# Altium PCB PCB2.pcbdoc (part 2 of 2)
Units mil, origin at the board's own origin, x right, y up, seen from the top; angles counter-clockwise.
Board outline 4645 x 3125 mil, 2 copper layers (Top Layer, Bottom Layer); 221 components, 102 nets, 399 pads, 608 vias.
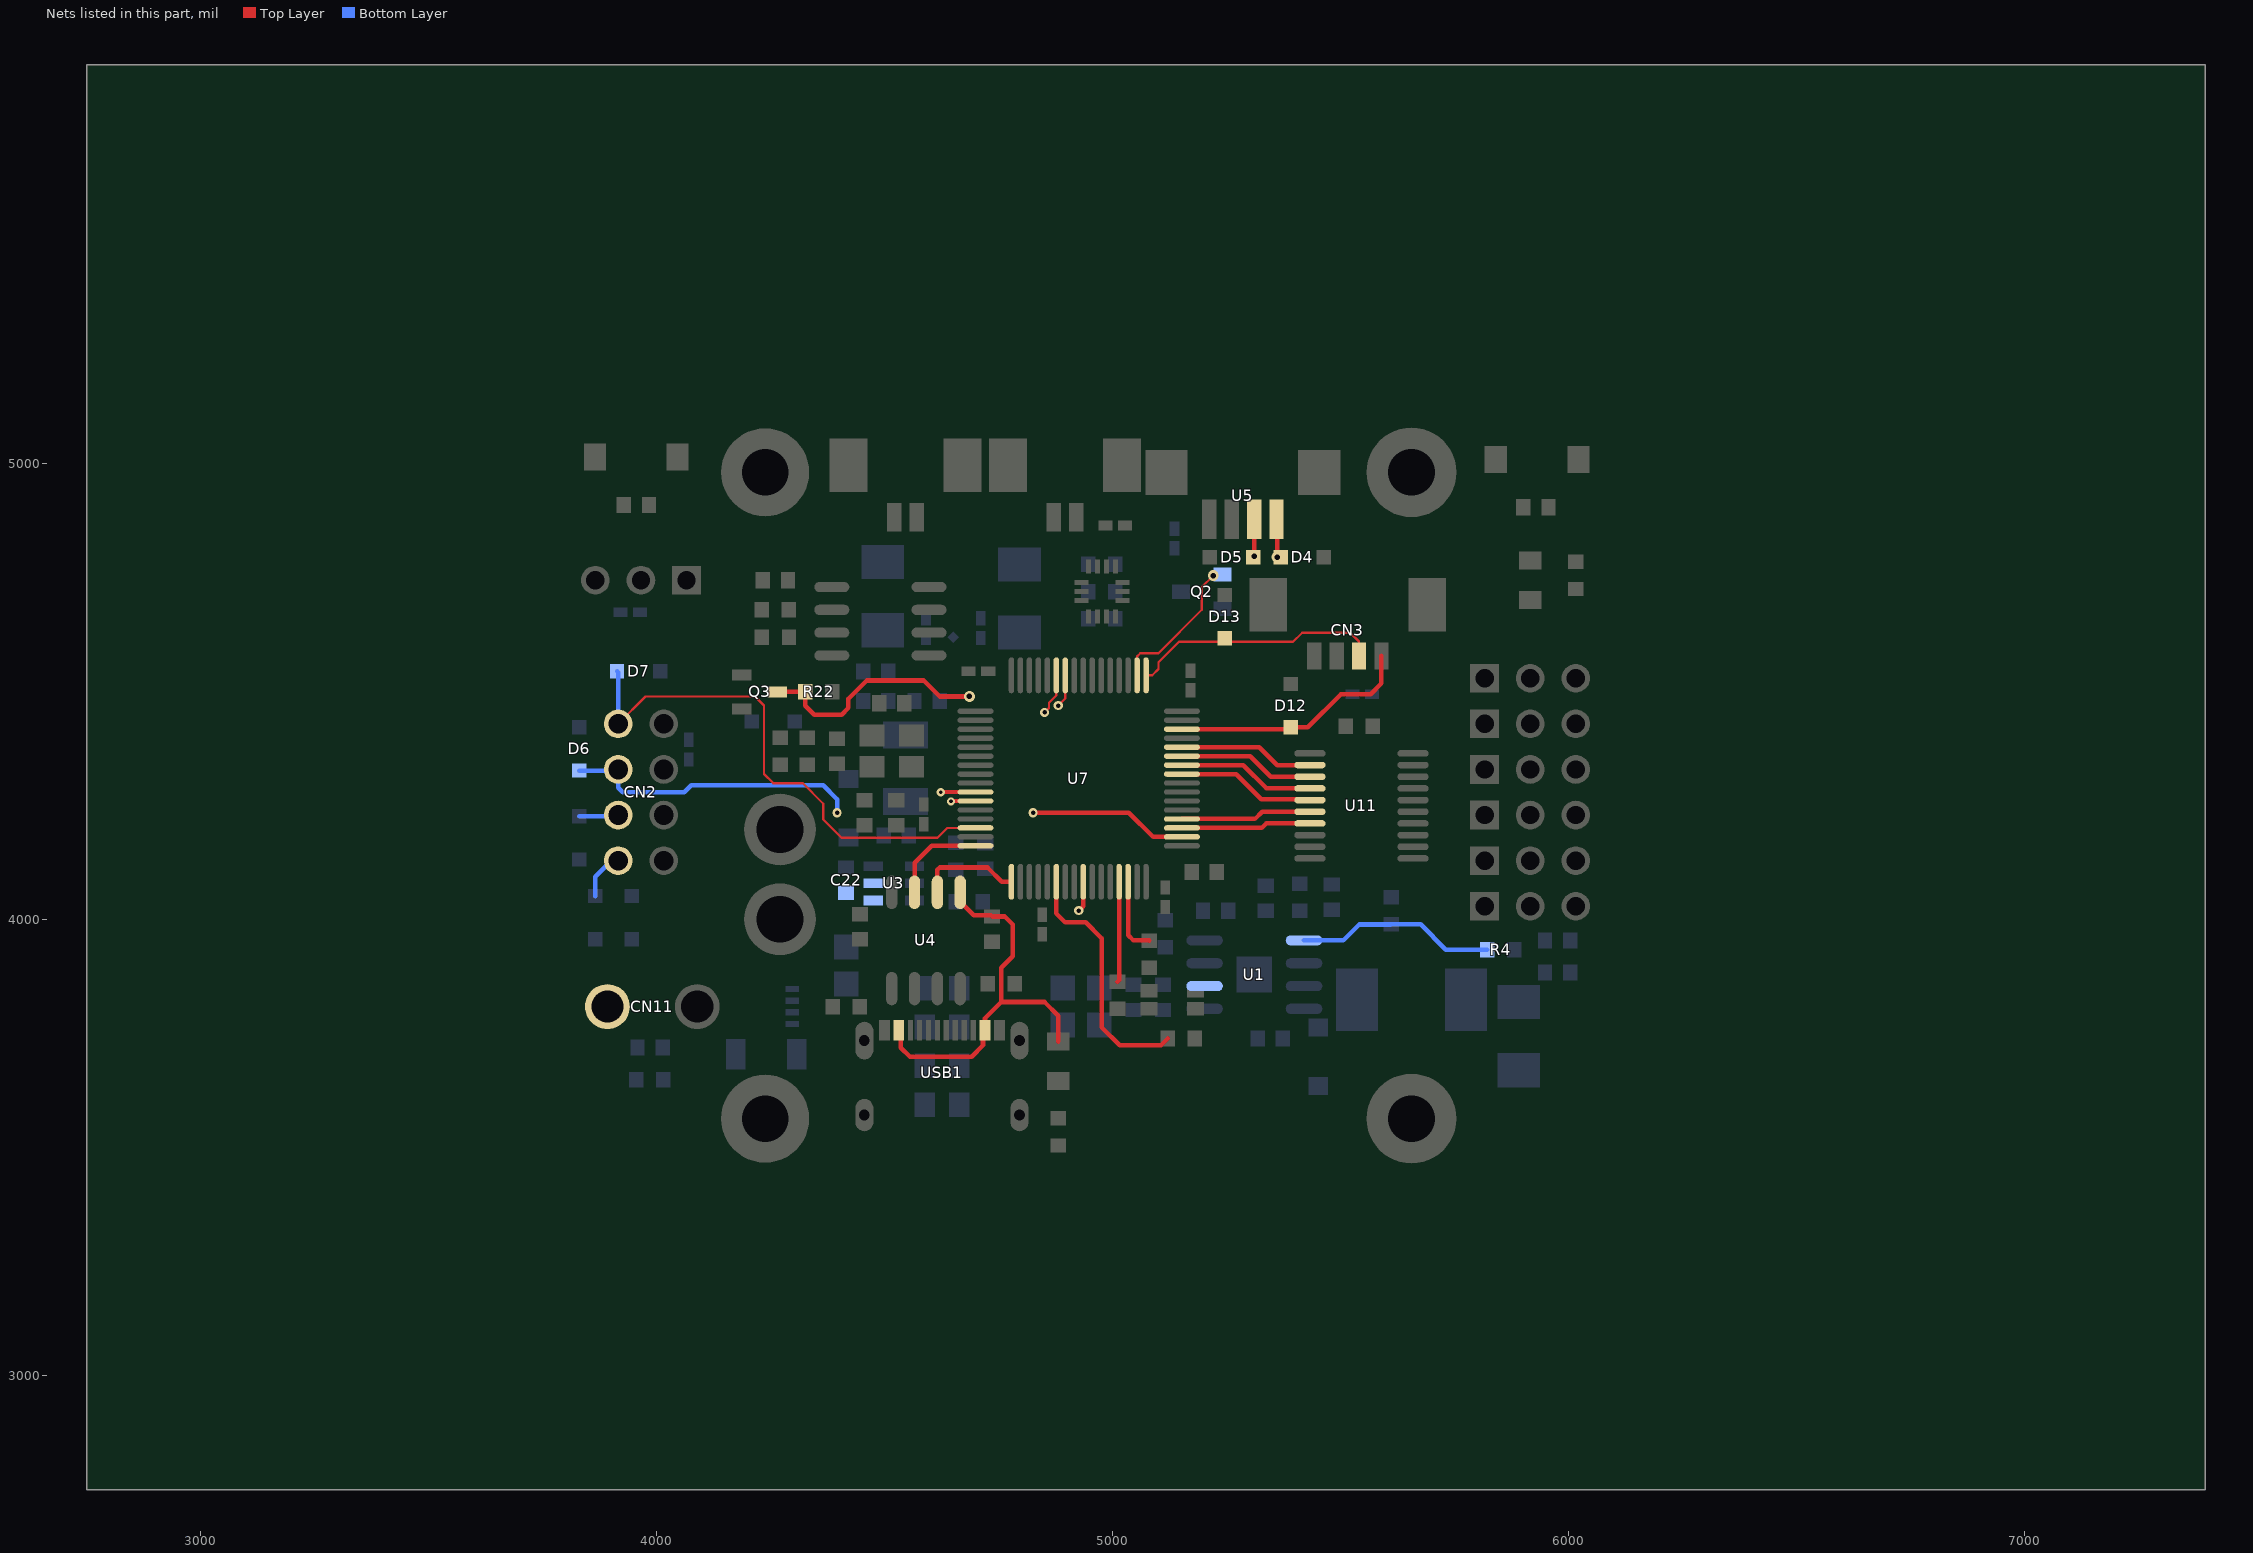
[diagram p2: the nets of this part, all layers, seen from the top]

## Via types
v1: diameter 17.76, hole 9.65, Top Layer to Bottom Layer, 499 vias
v2: diameter 24.02, hole 12.01, Top Layer to Bottom Layer, 75 vias
v3: diameter 17.76, hole 8, Top Layer to Bottom Layer, 19 vias
v4: diameter 20, hole 10, Top Layer to Bottom Layer, 11 vias
v5: diameter 24, hole 12, Top Layer to Bottom Layer, 4 vias

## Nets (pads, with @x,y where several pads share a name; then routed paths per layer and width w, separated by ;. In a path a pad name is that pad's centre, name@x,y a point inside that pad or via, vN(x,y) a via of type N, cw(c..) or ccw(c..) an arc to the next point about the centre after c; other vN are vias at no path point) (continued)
SPI2_CS: CN2.1 D7.1 U7.14 | length 1170.3
  Top Layer w5: CN2.1@3915,4430 3975,4490 4215,4490 4235,4470 4235,4320 4255,4300 4320,4300 4365,4255 4365,4220 4405,4180 4615,4180 4636.73,4201.73 U7.14@4698.63,4201.73
  Bottom Layer w10: D7.1@3912.6,4545 3915,4542.6 CN2.1@3915,4430
SPI2_MISO: CN2.7 U7.10 | length 1164.3
  Top Layer w8: v3(4622.37,4280) 4622.84,4280.47 U7.10@4698.63,4280.47
  Mid-Layer 2 w10: CN2.7@3915,4130 3895,4130 3855,4170 3855,4255 3880,4280 4115,4280 4165,4330 4345,4330 4395,4280 v3(4622.37,4280)
  Bottom Layer w10: 3865,4052.4 3865,4095 3900,4130 CN2.7@3915,4130
SPI2_MOSI: CN2.5 U7.11 | length 964.6
  Top Layer w8: v3(4645,4260) 4645.79,4260.79 U7.11@4698.63,4260.79
  Mid-Layer 2 w10: CN2.5@3915,4230 3915,4210 3945,4180 4100,4180 4215,4295 4355,4295 4390,4260 v3(4645,4260)
  Bottom Layer w10: 3830,4227.4 3912.4,4227.4 CN2.5@3915,4230
SPI2_SCL: CN2.3 D6.1 U7.34 | length 1437.1
  Top Layer w10: v4(4825,4235) 5035,4235 5087.95,4182.05 U7.34@5151.37,4182.05
  Mid-Layer 2 w10: v4(4395,4235) v4(4825,4235)
  Bottom Layer w10: D6.1@3830,4327.6 3912.6,4327.6 CN2.3@3915,4330 3915,4290 3925,4280 4060,4280 4075,4295 4365,4295 4395,4265 v4(4395,4235)
SWD_CLK: CN3.2 D13.1 U7.49 | length 554.1
  Top Layer w5: U7.49@5072.64,4536.37 5086.37,4536.37 5100,4550 5100,4565 5145,4610 5395,4610 5415,4630 5520,4630 5539.6,4610.4 CN3.2@5539.6,4578.9
SWD_IO: D12.1 U7.46 | length 539.2
  Top Layer w10: U7.46@5151.37,4418.27 5385.67,4418.27 D12.1@5390,4422.6 5427.6,4422.6 5500,4495 5565,4495 5588.8,4518.8 5588.8,4578.9
TIM1_CH1: U7.41 U11.5 | length 304.2
  Top Layer w10: U7.41@5151.37,4319.84 5270.16,4319.84 5325,4265 5429.76,4265 U11.5@5431.97,4262.79
TIM1_CH2: U7.42 U11.4 | length 301.8
  Top Layer w10: U7.42@5151.37,4339.53 5285.47,4339.53 5336.61,4288.39 U11.4@5431.97,4288.39
TIM1_CH3: U7.43 U11.3 | length 299.3
  Top Layer w10: U7.43@5151.37,4359.21 5300.79,4359.21 5346.02,4313.98 U11.3@5431.97,4313.98
TIM1_CH4: U7.44 U11.2 | length 296.9
  Top Layer w10: U7.44@5151.37,4378.9 5321.1,4378.9 5360.43,4339.57 U11.2@5431.97,4339.57
TIM2_CH1: Q2.1 U7.50 | length 311.3
  Top Layer w5: U7.50@5052.95,4536.37 5052.95,4577.95 5060,4585 5100,4585 5195,4680 5195,4730 v2(5220,4755)
TIM2_CH2: 
TIM2_CH3: U7.29 | length 220.5
  Top Layer w10: 5010,3864.66 5013.58,3868.24 U7.29@5013.58,4083.63
TIM2_CH4: U7.30 | length 168.6
  Top Layer w10: U7.30@5033.27,4083.63 5033.27,3966.73 5045,3955 5079.66,3955 5080,3954.66
TIM15_CH1: U7.35 U11.7 | length 284.7
  Top Layer w10: U7.35@5151.37,4201.73 5326.73,4201.73 5336.61,4211.61 U11.7@5431.97,4211.61
TIM15_CH2: U7.36 U11.6 | length 287.1
  Top Layer w10: U7.36@5151.37,4221.42 5311.42,4221.42 5327.2,4237.2 U11.6@5431.97,4237.2
TIM16_CH1: U7.22 | length 554.2
  Top Layer w10: U7.22@4875.79,4083.63 4875.79,4014.21 4895,3995 4940,3995 4975,3960 4975,3765 5015,3725 5105.34,3725 5120.34,3740
UART1_RX: D4.1 U5.1 U7.59 | length 915.6
  Top Layer w5: v4(4850,4455) 4860,4465 4860,4476.16 4875.79,4491.95 U7.59@4875.79,4536.37
  Top Layer w10: U5.1@5358.82,4878.97 5360,4877.79 v2(5360,4795.57)
  Mid-Layer 2 w10: v4(4850,4455) 4900,4405 5050,4405 5360,4715 v2(5360,4795.57)
UART1_TX: D5.1 U5.2 U7.58 | length 811.5
  Top Layer w5: v4(4880,4470) 4895.47,4485.47 U7.58@4895.47,4536.37
  Top Layer w10: U5.2@5309.6,4878.97 5310,4878.57 v2(5310,4797.05)
  Mid-Layer 2 w10: v4(4880,4470) 4925,4425 5030,4425 5310,4705 v2(5310,4797.05)
UART2_RX: U4.6 U7.17 | length 226.8
  Top Layer w10: U4.6@4615,4060.61 4615,4110 4620,4115 4725,4115 4756.37,4083.63 U7.17@4777.36,4083.63
UART2_TX: U4.7 U7.16 | length 213.5
  Top Layer w10: U4.7@4565,4060.61 4565,4125 4602.36,4162.36 U7.16@4698.63,4162.36
UART3_RX: Q3.3 R22.1 U7.25 | length 1185.4
  Top Layer w10: Q3.3@4263.98,4500 R22.1@4325.68,4500 4325.68,4469.32 4345,4450 4405,4450 4420,4465 4420,4485 4460,4525 4585,4525 4620,4490 v2(4685,4490) ; v4(4925,4020.46) 4934.84,4030.3 U7.25@4934.84,4083.63
  Mid-Layer 2 w10: v2(4685,4490) 4740,4490 4925,4305 v4(4925,4020.46)
UART3_TX: 
USB_5V: U4.5 USB1.A4B9 USB1.B4A9 | length 880.9
  Top Layer w10: USB1.A4B9@4530.5,3758 4535,3753.5 4535,3720 4555,3700 4690,3700 4715,3725 4715,3753.5 USB1.B4A9@4719.5,3758 4719.5,3784.5 4755,3820 ; U4.5@4665,4060.61 4665,4040 4695,4010 4732.56,4010 4735,4007.56 4762.44,4007.56 4780,3990 4780,3920 4755,3895 4755,3820 ; 4880,3733.31 4880,3790 4850,3820 4755,3820
VCC: C22.1 CN11.2 U1.2 U3.4 U3.5
VREF1: R4.1 U1.5 | length 438.9
  Bottom Layer w10: U1.5@5419,3955 5505,3955 5540,3990 5609.66,3990 5610,3990.34 5674.66,3990.34 5730,3935 R4.1@5820.34,3935
"": 
pads on no net: C1.2 C2.2 C3.2 C4.2 C5.2 C6.2 C7.2 C8.2 C9.2 C10.2 C11.2 C12.1 C13.2 C14.2 C15.2 C16.2 C17.2 C18.1 C19.1 C20.2 C21.2 C22.2 C23.2 C24.2 C25.2 C26.2 C27.2 C28.2 C29.2 C30.2 C31.2 C32.2 C33.2 C34.2 C35.2 C36.2 C37.2 C38.2 C39.2 C40.2 C41.2 C42.2 C43.2 CN2.8 CN3.1 CN11.1 CN12.1 D1.1 D2.2 D3.1 D4.2 D5.2 D6.2 D7.2 D8.2 D9.2 D10.2 D11.2 D12.2 D13.2 H1.1 H4.1 L1.1 L2.2 LED1.2 LED2.2 LED3.1 Q1.4 Q2.2 Q3.1 R1.2 R2.2 R3.2 R4.2 R5.2 R6.2 R7.2 R8.2 R9.2 R10.2 R11.2 R12.2 R13.2 R14.2 R15.2 R16.2 R17.2 R18.2 R19.2 R20.2 R21.2 R22.2 R23.2 R24.2 R25.2 R26.2 R27.2 SW1.2 SW2.2 U1.1 U2.5 U3.6 U4.1 U4.4 U5.6 U6.1 U7.2 U7.3 U7.4 U7.15 U7.20 U7.21 U7.23 U7.24 U7.27 U7.28 U7.37 U7.38 U7.39 U7.40 U7.51 U7.64 U8.1 U8.2 U8.3 U8.10 U8.11 U9.1 U10.1 U11.1 U11.8 U11.9 U11.11 U11.12 U23.3 U24.3 U25.3 U26.3 U27.3 U28.3 U29.3 USB1.A1B12 USB1.A8 USB1.B8 X1.1
copper on no net:
  other v5: 5290.3,3860.3 5329.7,3860.3 5290.3,3899.7 5329.7,3899.7

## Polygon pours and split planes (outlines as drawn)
GND on Mid-Layer 1 (solid, remove dead copper, pour order 2): 3460,3165 6640,3165 6640,5340 3460,5340
GND on Top Layer (solid, remove dead copper, pour order 4): 3115,3000 6910,3000 6910,5540 3115,5540
GND on Mid-Layer 2 (solid, remove dead copper, pour order 5): 3000,3030 7145,3030 7145,5625 3000,5625
GND on Bottom Layer (solid, remove dead copper, pour order 6): 3415,3210 6460,3210 6460,5410 3415,5410
PGND on Mid-Layer 1 (solid, remove dead copper): 4625,3391.93 4625,3905 5050.31,3905 5055.9,3899.41 5055.9,4026.87 5054.24,4028.54 5154.59,4028.54 5155,4028.13 5155,4059.78 5279.78,4059.78 5280,4060 5280,4105 5701.03,4105 5701.3,4104.73 5759.73,4104.73 5760,4105 5760,4600 6180,4600 6180,3395 6185,3390 4626.93,3390
PGND on Bottom Layer (solid, remove dead copper, pour order 1): 5279.78,4059.78 5280,4060 5280,4105 5701.03,4105 5701.3,4104.73 5759.73,4104.73 5760,4105 5760,4600 6180,4600 6180,3395 6185,3390 4626.93,3390 4625,3391.93 4625,3905 4955,3905 4955,4060
PGND on Top Layer (solid, remove dead copper, pour order 3): 5279.78,4059.78 5280,4060 5280,4105 5701.03,4105 5701.3,4104.73 5759.73,4104.73 5760,4105 5760,4600 6180,4600 6180,3395 6185,3390 4626.93,3390 4625,3391.93 4625,3905 4955,3905 4955,4060

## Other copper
Top Layer:
  region net VCC: 3780,3755 3980,3755 4005,3780 4005,3860 4044.2,3899.2 4348.7,3899.2 4348.7,4083.7 4350,4085 4156.6,4085 4111.6,4040 3785,4040 3780,4035
  pour cut-out net $1N6780: 5982.99,4793.31 5982.99,4783.31 5997.99,4770.81 5997.99,4800.88
  pour cut-out net PGND: 6020,4694.8 6032.01,4709.8 5997.99,4709.8 6010,4694.8
  pour cut-out net SER.5V: 5920,4667.01 5932.5,4682.01 5897.5,4682.01 5910,4667.01
  pour cut-out net $1N6780: 5954.61,4793.31 5939.61,4805.81 5939.61,4770.81 5954.61,4783.31
  pour cut-out net USB_5V: 4710,3725 4720,3725 4731.3,3735.35 4707.7,3735.35
  pour cut-out net USB_5V: 4714.5,3784.5 4707.7,3780.65 4731.3,3780.65 4724.5,3784.5
  pour cut-out net $2N2059: 4689.9,3792.65 4688,3780.65 4699.8,3780.65 4697.9,3792.65
  pour cut-out net DP: 4650.5,3790.5 4648.6,3780.65 4660.4,3780.65 4658.5,3790.5
  pour cut-out net DN: 4631,3725 4639,3725 4640.7,3735.35 4628.9,3735.35
  pour cut-out net DP: 4611.2,3784.8 4609.3,3780.65 4621.1,3780.65 4619.2,3784.8
  pour cut-out net DN: 4591.5,3784.5 4589.6,3780.65 4601.4,3780.65 4599.5,3784.5
  pour cut-out net DN: 4599.5,3724.5 4601.4,3735.35 4589.6,3735.35 4591.5,3724.5
  pour cut-out net $2N2060: 4571.8,3784.2 4569.9,3780.65 4581.7,3780.65 4579.8,3784.2
  pour cut-out net $2N2059: 4721.34,3840 4729.34,3840 4739.34,3842.99 4711.34,3842.99
  pour cut-out net DP: 4534.16,3888.5 4528.06,3893.71 4502.6,3873.7 4527.4,3867.6
  pour cut-out net $2N2114: 4487.6,4055.61 4502.6,4043.11 4502.6,4078.11 4487.6,4065.61
  pour cut-out net UART2_TX: 4570,4111.27 4560,4111.27 4552.6,4084.92 4577.4,4084.92
  pour cut-out net UART2_RX: 4610,4110 4602.6,4084.92 4627.4,4084.92 4620,4110
  pour cut-out net USB_5V: 4682.53,4015.4 4687.91,4024.16 4677.4,4052.35 4652.6,4036.3
  pour cut-out net USB_5V: 4762.44,4002.56 4762.44,4012.56 4752.72,4023.31 4752.72,3991.81
  pour cut-out net USB_5V: 4702.28,4005 4717.28,3992.5 4717.28,4023.31 4702.28,4015
  pour cut-out net $2N2114: 4450,4035 4440,4035 4427.5,4028.31 4462.5,4028.31
  pour cut-out net USB_5V: 4885,3767.99 4875,3767.99 4862.5,3752.99 4897.5,3752.99
  pour cut-out net $2N2074: 4875,3612 4885,3612 4897.5,3627 4862.5,3627
  pour cut-out net $2N2074: 4875,3595.54 4862.99,3580.54 4897.01,3580.54 4885,3595.54
  pour cut-out net 3V3: 4756.45,4531.37 4771.45,4518.87 4771.45,4553.87 4756.45,4541.37
  pour cut-out net CAN_TX: 4811.73,4587.98 4810.82,4569.83 4822.64,4569.83 4821.73,4587.98
  pour cut-out net CAN_RX: 4831.42,4587.98 4830.51,4569.83 4842.33,4569.83 4841.42,4587.98
  pour cut-out net UART1_RX: 4878.29,4491.95 4881.7,4502.91 4869.88,4502.91 4873.29,4491.95
  pour cut-out net UART1_TX: 4892.97,4490.06 4897.97,4490.06 4901.38,4502.91 4889.56,4502.91
  pour cut-out net SPI1_MOSI: 4910.16,4484.76 4920.16,4484.76 4921.07,4502.91 4909.25,4502.91
  pour cut-out net SPI1_MISO: 4937.34,4582.68 4932.34,4582.68 4928.93,4569.83 4940.75,4569.83
  pour cut-out net SPI1_CS: 4969.21,4490.79 4979.21,4490.79 4980.12,4502.91 4968.3,4502.91
  pour cut-out net BMI160_INT1: 4996.4,4582.68 4991.4,4582.68 4987.99,4569.83 4999.81,4569.83
  pour cut-out net TIM2_CH1: 5050.45,4577.95 5047.04,4569.83 5058.86,4569.83 5055.45,4577.95
  pour cut-out net SWD_CLK: 5086.05,4538.87 5078.55,4545.12 5078.55,4527.62 5086.05,4533.87
  pour cut-out net 3V3: 5160.81,4474.15 5117.91,4463.55 5170.21,4451.73 5173.54,4472.73
  pour cut-out net SWD_IO: 5202.98,4423.27 5184.83,4424.18 5184.83,4412.36 5202.98,4413.27
  pour cut-out net DIR: 5202.98,4403.58 5184.83,4404.49 5184.83,4392.67 5202.98,4393.58
  pour cut-out net TIM1_CH4: 5202.98,4383.9 5184.83,4384.81 5184.83,4372.99 5202.98,4373.9
  pour cut-out net TIM1_CH3: 5202.98,4364.21 5184.83,4365.12 5184.83,4353.3 5202.98,4354.21
  pour cut-out net TIM1_CH2: 5202.98,4334.53 5202.98,4344.53 5184.83,4345.44 5184.83,4333.62
  pour cut-out net TIM1_CH1: 5202.98,4324.84 5184.83,4325.75 5184.83,4313.93 5202.98,4314.84
  pour cut-out net TIM15_CH2: 5202.98,4226.42 5184.83,4227.33 5184.83,4215.51 5202.98,4216.42
  pour cut-out net TIM15_CH1: 5202.98,4206.73 5184.83,4207.64 5184.83,4195.82 5202.98,4196.73
  pour cut-out net SPI2_SCL: 5099.76,4177.05 5117.91,4176.14 5117.91,4187.96 5099.76,4187.05
  pour cut-out net SERVO_EN: 5192.64,4167.36 5184.83,4168.27 5184.83,4156.45 5192.64,4157.36
  pour cut-out net 3V3: 5088.35,4075 5078.55,4117.09 5066.73,4064.79 5081.27,4067.92
  pour cut-out net TIM2_CH4: 5038.27,4032.02 5039.18,4050.17 5027.36,4050.17 5028.27,4032.02
  pour cut-out net TIM2_CH3: 5018.58,4032.02 5019.49,4050.17 5007.67,4050.17 5008.58,4032.02
  pour cut-out net KEY: 4959.53,4032.02 4960.44,4050.17 4948.62,4050.17 4949.53,4032.02
  pour cut-out net UART3_RX: 4939.84,4032.02 4940.75,4050.17 4928.93,4050.17 4929.84,4032.02
  pour cut-out net TIM16_CH1: 4870.79,4032.02 4880.79,4032.02 4881.7,4050.17 4869.88,4050.17
  pour cut-out net 3V3: 4821.73,4039.73 4822.64,4050.17 4810.82,4050.17 4811.73,4039.73
  pour cut-out net 3V3: 4811.73,4135.24 4810.82,4117.09 4822.64,4117.09 4821.73,4135.24
  pour cut-out net UART2_RX: 4756.45,4088.63 4756.45,4078.63 4771.45,4066.13 4771.45,4101.13
  pour cut-out net UART2_TX: 4647.02,4157.36 4665.17,4156.45 4665.17,4168.27 4647.02,4167.36
  pour cut-out net SPI2_CS: 4652.32,4199.23 4665.17,4195.82 4665.17,4207.64 4652.32,4204.23
  pour cut-out net 3V3: 4647.02,4226.42 4647.02,4216.42 4665.17,4215.51 4665.17,4227.33
  pour cut-out net 3V3: 4750.24,4226.42 4732.09,4227.33 4732.09,4215.51 4750.24,4216.42
  pour cut-out net SPI2_MOSI: 4648.82,4256.79 4665.17,4254.88 4665.17,4266.7 4648.82,4264.79
  pour cut-out net SPI2_MISO: 4648.82,4276.47 4665.17,4274.56 4665.17,4286.38 4648.82,4284.47
  pour cut-out net I2C3_SDA: 4648.82,4296.16 4665.17,4294.25 4665.17,4306.07 4648.82,4304.16
  pour cut-out net I2C3_SCL: 4648.82,4315.84 4665.17,4313.93 4665.17,4325.75 4648.82,4323.84
  pour cut-out net RST: 4646.38,4335 4665.17,4333.62 4665.17,4345.44 4647.94,4345
  pour cut-out net OSC_OUT: 4652.32,4356.71 4665.17,4353.3 4665.17,4365.12 4652.32,4361.71
  pour cut-out net OSC_IN: 4652.32,4381.4 4652.32,4376.4 4665.17,4372.99 4665.17,4384.81
  pour cut-out net 3V3: 4750.24,4462.64 4732.09,4463.55 4732.09,4451.73 4750.24,4452.64
  pour cut-out net CAN_TX: 4648.71,4575 4648.71,4585 4623.7,4591.19 4623.7,4568.81
  pour cut-out net 5V: 4544.29,4675 4569.3,4668.81 4569.3,4691.19 4544.29,4685
  pour cut-out net CAN_RX: 4648.71,4735 4623.7,4741.19 4623.7,4718.81 4648.71,4725
  pour cut-out net CAN_H: 4331.29,4625 4356.3,4618.81 4356.3,4641.19 4331.29,4635
  pour cut-out net CAN_H: 4435,4635 4410.7,4641.19 4410.7,4618.81 4435,4625
  pour cut-out net CAN_L: 4331.29,4685 4331.29,4675 4356.3,4668.81 4356.3,4691.19
  pour cut-out net CAN_L: 4430,4685 4410.7,4691.19 4410.7,4668.81 4430,4675
  pour cut-out net $2N14786: 4335,4735 4335,4725 4356.3,4718.81 4356.3,4741.19
  pour cut-out net UART1_TX: 5305,4820.67 5315,4820.67 5325.35,4835.67 5293.85,4835.67
  pour cut-out net UART1_RX: 5365,4820.67 5374.57,4835.67 5343.07,4835.67 5355,4820.67
  pour cut-out net CAN_L: 4564.6,4929.1 4553.85,4914.41 4585.35,4914.41 4574.6,4929.1
  pour cut-out net CAN_H: 4525.39,4840.56 4536.14,4851.42 4504.65,4851.42 4515.39,4840.56
  pour cut-out net CAN_L: 4924.6,4915.4 4914.6,4915.4 4903.85,4914.41 4935.35,4914.41
  pour cut-out net CAN_H: 4839.65,4887.91 4839.65,4877.91 4854.65,4865.41 4854.65,4900.41
  pour cut-out net $2N14800: 5075,3874.45 5062.5,3859.45 5097.5,3859.45 5085,3874.45
  pour cut-out net 3V3: 5176.18,3874.45 5163.68,3859.45 5198.68,3859.45 5186.18,3874.45
  pour cut-out net $2N14802: 5045.12,3810.34 5045.12,3800.34 5060.12,3790.55 5060.12,3820.08
  pour cut-out net $2N14801: 5186.18,3775.55 5198.68,3790.55 5163.68,3790.55 5176.18,3775.55
  pour cut-out net DIR: 5384.56,4370 5384.87,4360 5404.84,4357.99 5404.84,4372.33
  pour cut-out net DIR: 5479.23,4370.16 5459.1,4372.33 5459.1,4357.99 5479.23,4360.16
  pour cut-out net TIM1_CH4: 5384.71,4344.57 5384.71,4334.57 5404.84,4332.4 5404.84,4346.74
  pour cut-out net TIM1_CH3: 5384.71,4318.98 5384.71,4308.98 5404.84,4306.81 5404.84,4321.15
  pour cut-out net TIM1_CH2: 5384.71,4283.39 5404.84,4281.22 5404.84,4295.56 5384.71,4293.39
  pour cut-out net TIM15_CH2: 5384.71,4242.2 5384.71,4232.2 5404.84,4230.03 5404.84,4244.37
  pour cut-out net TIM15_CH1: 5384.71,4216.61 5384.71,4206.61 5404.84,4204.44 5404.84,4218.78
  pour cut-out net 5V: 5652.03,4390.33 5637.03,4372.33 5679.03,4372.33 5664.03,4390.33
  pour cut-out net SER.6: 5698.98,4318.98 5685.16,4321.15 5685.16,4306.81 5698.98,4308.98
  pour cut-out net SER.5: 5705.29,4293.39 5685.16,4295.56 5685.16,4281.22 5705.29,4283.39
  pour cut-out net SER.4: 5705.29,4267.79 5685.16,4269.96 5685.16,4255.62 5705.29,4257.79
  pour cut-out net SER.3: 5705.29,4242.2 5685.16,4244.37 5685.16,4230.03 5705.29,4232.2
  pour cut-out net SER.2: 5705.29,4216.61 5685.16,4218.78 5685.16,4204.44 5705.29,4206.61
  pour cut-out net SER.1: 5705.29,4191.02 5685.16,4193.19 5685.16,4178.85 5705.29,4181.02
  pour cut-out net OSC_IN: 4590.55,4406.95 4585.87,4413.2 4585.87,4395.7 4590.55,4401.95
  pour cut-out net OSC_IN: 4547.56,4443.07 4537.56,4443.07 4530.75,4428.07 4560.06,4428.07
  pour cut-out net OSC_OUT: 4429.13,4347.44 4429.13,4337.44 4444.13,4324.94 4444.13,4359.17
  pour cut-out net OSC_OUT: 4504.15,4364.48 4497.08,4364.48 4482.94,4359.17 4499.25,4350.73
  pour cut-out net CAN_H: 4320.54,4625 4320.54,4635 4305.54,4637.01 4305.54,4612.5
  pour cut-out net $2N14786: 4225.34,4652.01 4214.46,4637.01 4246.22,4637.01 4235.34,4652.01
  pour cut-out net CAN_L: 4320.2,4685 4305.2,4697.01 4305.2,4662.99 4320.2,4675
  pour cut-out net $2N14786: 4225.34,4647.99 4235.34,4647.99 4245.88,4697.01 4214.12,4697.01
  pour cut-out net $2N14786: 4225.34,4712.01 4214.12,4697.01 4245.88,4697.01 4235.34,4712.01
  pour cut-out net $2N14786: 4227.44,4772.44 4216.69,4762.72 4248.19,4762.72 4237.44,4772.44
  pour cut-out net $2N14786: 4225.34,4712.28 4235.34,4712.28 4247.84,4727.28 4216.69,4727.28
  pour cut-out net TIM2_CH4: 5047.99,3960 5047.99,3950 5062.99,3938.78 5062.99,3970.54
  pour cut-out net $2N14800: 5075,3864.46 5085,3864.46 5097.01,3879.46 5062.99,3879.46
  pour cut-out net $2N14801: 5186.18,3772.01 5176.18,3772.01 5163.78,3757.01 5195.54,3757.01
  pour cut-out net TIM2_CH3: 5018.58,3895.54 5008.58,3895.54 4996.08,3880.54 5027.01,3880.54
  pour cut-out net $2N14802: 5042.01,3810.34 5027.01,3821.22 5027.01,3789.46 5042.01,3800.34
  pour cut-out net RST: 3896.69,4915 3896.69,4905 3911.69,4892.5 3911.69,4927.5
  pour cut-out net KEY: 5869.13,4910 5869.13,4900 5884.13,4887.5 5884.13,4922.5
  pour cut-out net SWD_IO: 5583.8,4534.35 5593.8,4534.35 5604.55,4549.35 5573.05,4549.35
  pour cut-out net SWD_CLK: 5542.1,4610.4 5537.1,4610.4 5530.85,4608.45 5548.35,4608.45
  pour cut-out net 3V3: 5395.45,4595 5395.45,4575 5425.45,4550 5425.45,4608.45
  pour cut-out net SWD_CLK: 5268.25,4607.5 5268.25,4612.5 5260.75,4618.75 5229.25,4601.85
  pour cut-out net SWD_CLK: 5221.75,4607.5 5229.25,4601.85 5229.25,4618.75 5221.75,4612.5
  pour cut-out net SWD_IO: 5359.25,4423.27 5359.25,4413.27 5374.25,4406.85 5374.25,4435.77
  pour cut-out net SWD_IO: 5420.75,4427.6 5405.75,4438.35 5405.75,4406.85 5420.75,4417.6
  pour cut-out net RST: 3869.4,4970.45 3881.9,4985.45 3846.9,4985.45 3859.4,4970.45
  pour cut-out net KEY: 5844.4,4965.45 5856.9,4980.45 5821.9,4980.45 5834.4,4965.45
  pour cut-out net UART1_RX: 5365,4825.75 5355,4825.75 5351.85,4810.75 5377.5,4810.75
  pour cut-out net UART1_TX: 5305,4825.75 5292.5,4810.75 5323.15,4810.75 5315,4825.75
  pour cut-out net OSC_IN: 4547.56,4442.28 4558.31,4457.28 4526.81,4457.28 4537.56,4442.28
  pour cut-out net OSC_OUT: 4427.72,4347.44 4412.72,4358.19 4412.72,4326.69 4427.72,4337.44
  pour cut-out net 5V: 5603.54,4414 5603.54,4426 5585.54,4441 5585.54,4407.99
  pour cut-out net DIR: 5505.34,4392.99 5515.34,4392.99 5526.22,4407.99 5494.46,4407.99
  pour cut-out net 3V3: 4559.37,4212.44 4559.37,4202.44 4574.37,4194.45 4574.37,4224.94
  pour cut-out net 3V3: 4610.63,4215 4595.63,4225.55 4595.63,4194.45 4610.63,4205
  pour cut-out net 3V3: 4736.46,4585.63 4716.46,4585.63 4710.91,4555.63 4742.01,4555.63
  pour cut-out net 3V3: 4736.46,4508.54 4742.01,4534.37 4710.91,4534.37 4716.46,4508.54
  pour cut-out net 3V3: 5165,4476.27 5175,4476.27 5180.63,4487.99 5159.37,4487.99
  pour cut-out net 3V3: 5129.37,4513.54 5129.37,4493.54 5159.37,4487.99 5159.37,4519.09
  pour cut-out net 3V3: 5089.37,4076.46 5089.37,4066.46 5104.37,4055.91 5104.37,4087.01
  pour cut-out net 3V3: 5115,4102.01 5104.37,4087.01 5125.63,4087.01 5125,4102.01
  pour cut-out net 3V3: 4825.91,4037.62 4823.76,4025.63 4834.37,3995.91 4854.2,4027.01
  pour cut-out net 3V3: 5176.18,4072.28 5186.18,4072.28 5188.19,4087.28 5163.68,4087.28
  pour cut-out net 3V3: 5126.69,4115 5126.69,4095 5156.69,4087.28 5156.69,4122.72
  pour cut-out net 3V3: 4492.28,4212.44 4492.28,4202.44 4507.28,4191.69 4507.28,4223.19
  pour cut-out net 3V3: 4557.72,4212.44 4542.72,4223.19 4542.72,4191.69 4557.72,4202.44
  pour cut-out net 3V3: 4432.56,4204.94 4437.28,4198.69 4437.28,4216.19 4432.56,4209.94
  pour cut-out net 3V3: 4487.72,4212.44 4472.72,4223.19 4472.72,4191.69 4487.72,4202.44
  pour cut-out net SPI1_MISO: 4949.07,4643.43 4952.08,4649.73 4941.06,4649.73 4944.07,4643.43
  pour cut-out net BMI160_INT1: 5008.13,4645.63 5011.14,4649.73 5000.12,4649.73 5003.13,4645.63
  pour cut-out net 3V3: 5005.31,4697.81 5005.63,4694.8 5005.63,4705.82 5005.31,4702.81
  pour cut-out net 3V3: 5001.63,4802.27 5000.12,4790.27 5011.14,4790.27 5009.63,4802.27
  pour cut-out net SPI1_CS: 4910.32,4737.18 4915.67,4734.17 4915.67,4745.19 4910.32,4742.18
  pour cut-out net SPI1_SCL: 4908.17,4717.5 4915.67,4714.49 4915.67,4725.51 4908.17,4722.5
  pour cut-out net SPI1_MOSI: 4933.62,4687.3 4939.87,4694.8 4922.37,4694.8 4928.62,4687.3
  pour cut-out net $2N33293: 4149.95,4542.4 4149.95,4532.4 4164.95,4525.59 4164.95,4549.21
  pour cut-out net UART3_RX: 4300.05,4505 4285.05,4511.81 4285.05,4488.19 4300.05,4495
  pour cut-out net 5V: 4380,4525 4369.12,4517.01 4400.88,4517.01 4390,4525
  pour cut-out net UART3_RX: 4320.68,4469.32 4330.68,4469.32 4341.56,4482.99 4309.8,4482.99
  pour cut-out net UART3_RX: 4294.8,4505 4294.8,4495 4309.8,4482.99 4309.8,4517.01
  pour cut-out net I2C3_SCL: 4035.84,4206.38 4068.55,4225 4068.55,4235 4035.84,4253.62
  pour cut-out net SPI2_CS: 3946.44,4428.03 3954.63,4466.1 3951.1,4469.63 3913.03,4461.44
  pour cut-out net SER.5V: 5938.63,4550.83 5920,4583.55 5910,4583.55 5891.38,4550.84
  pour cut-out net SER.6: 5772.89,4494.96 5779.96,4487.89 5808.25,4498.5 5783.5,4523.25
  pour cut-out net $2N33293: 4070,4698.5 4082.5,4713.5 4047.5,4713.5 4060,4698.5
  pour cut-out net SER.1: 5768.5,4035 5768.5,4025 5783.5,4012.5 5783.5,4047.5
  pour cut-out net SER.2: 5775,4135 5775,4125 5783.5,4112.5 5783.5,4147.5
  pour cut-out net SER.3: 5768.5,4242.2 5768.5,4232.2 5783.5,4219.7 5783.5,4254.7
  pour cut-out net SER.5: 5768.5,4435 5768.5,4425 5783.5,4412.5 5783.5,4447.5
  pour cut-out net SER.4: 5768.5,4335 5768.5,4325 5783.5,4312.5 5783.5,4347.5
  pour cut-out net 3V3: 4299.01,4344 4287.01,4354 4287.01,4326 4299.01,4336
  pour cut-out net 3V3: 4300.99,4344 4300.99,4336 4312.99,4326 4312.99,4354
  pour cut-out net 3V3: 4337.3,4319.16 4344.37,4319.16 4347.01,4325.37 4312.99,4324.46
  pour cut-out net I2C3_SDA: 4335,4375 4345,4375 4347.01,4383.78 4322.5,4383.78
  pour cut-out net $1N6767: 4026.3,3649.25 4031.58,3661.61 4025.93,3667.26 4013.57,3661.98
  pour cut-out net $1N6767: 4298.76,3713.71 4286.29,3708.7 4286.29,3700.7 4298.76,3695.69
  pour cut-out net 5V: 4485.99,4664.8 4490,4652.33 4500,4652.33 4504.01,4664.8
  pour cut-out net 5V: 4506.77,4670.37 4518.91,4675 4511.32,4685 4495.88,4684.71
  pour cut-out net BMI160_INT2: 4910.97,4795.12 4921.31,4802.5 4919.02,4807.5 4903.47,4811.5
  pour cut-out net SPI1_CS: 4890.99,4762.06 4897.5,4750 4902.5,4750 4909.01,4762.06
  pour cut-out net SPI1_SCL: 4909.01,4682.94 4902.5,4695.41 4897.5,4695.41 4890.99,4682.94
  pour cut-out net SPI1_MOSI: 4907.94,4630.28 4914.29,4636.79 4914.29,4641.79 4907.94,4648.29
  pour cut-out net SPI1_MOSI: 4922.6,4481.49 4920.16,4491.92 4910.16,4492.08 4907.61,4481.73
  pour cut-out net SPI1_SCL: 4963.46,4481.61 4960.96,4492 4950.96,4492 4948.46,4481.61
  pour cut-out net SPI1_CS: 4984.8,4451.98 4985,4463.86 4975,4469.63 4971.81,4459.48
  pour cut-out net BMI160_INT2: 5022.5,4486.61 5020,4497 5010,4497 5007.5,4486.61
  pour cut-out net SERVO_EN: 5205.63,4159.98 5196.51,4165.56 5189.44,4158.49 5195.02,4149.37
  pour cut-out net TIM2_CH1: 5208.02,4755.75 5203.8,4742.33 5207.33,4738.8 5220.75,4743.02
  pour cut-out net UART1_TX: 4889.98,4469.37 4893.79,4480.25 4890.25,4483.79 4879.37,4479.98
  pour cut-out net UART1_TX: 5319.01,4805 5315,4817.47 5305,4817.47 5300.99,4805
  pour cut-out net UART1_RX: 5369.01,4803.52 5365,4815.99 5355,4815.99 5350.99,4803.52
  pour cut-out net I2C3_SCL: 4202.06,4434.01 4189.59,4430 4189.59,4420 4202.06,4415.99
  pour cut-out net SPI2_SCL: 4831.61,4227.5 4842,4230 4842,4240 4831.61,4242.5
  pour cut-out net UART3_RX: 4934.98,4019.84 4938.38,4026.77 4931.3,4033.84 4924.37,4030.44
  pour cut-out net KEY: 4965.63,4029.98 4958.07,4034.01 4950.99,4026.93 4955.02,4019.37
  pour cut-out net KEY: 5891.94,4914.01 5879.47,4910 5879.47,4900 5891.94,4895.99
  pour cut-out net UART3_RX: 4677.06,4499.01 4664.59,4495 4664.59,4485 4677.06,4480.99
  pour cut-out net UART1_RX: 4859.98,4454.37 4861.77,4463.23 4858.23,4466.77 4849.37,4464.98
  pour cut-out net I2C3_SCL: 4627.76,4313.24 4637.03,4315.84 4637.17,4323.84 4628,4326.55
  pour cut-out net SPI2_MISO: 4628.58,4273.66 4637.67,4276.47 4637.24,4284.47 4627.88,4286.96
  pour cut-out net SPI2_MOSI: 4651.44,4253.89 4660.44,4256.79 4659.72,4264.79 4650.26,4267.15
  pour cut-out net I2C3_SDA: 4650.99,4293.45 4660.16,4296.16 4660.02,4304.16 4650.75,4306.76
  pour cut-out net RST: 4650.87,4333.34 4660.09,4335 4660.09,4345 4650.87,4346.66
  pour cut-out net I2C3_SDA: 4346.66,4380.87 4345,4389.66 4335,4389.66 4333.34,4380.87
Mid-Layer 1:
  pour cut-out net BMI160_INT2: 4907.94,4790.99 4920.41,4797.5 4920.41,4802.5 4907.94,4809.01
  pour cut-out net SPI1_CS: 4907.94,4760.99 4920.41,4767.5 4920.41,4772.5 4907.94,4779.01
  pour cut-out net SPI1_CS: 4984.8,4451.98 4982.5,4465.3 4977.5,4468.19 4971.81,4459.48
  pour cut-out net BMI160_INT2: 5022.5,4486.61 5011.54,4497 5004.46,4497 5007.5,4486.61
Mid-Layer 2:
  pour cut-out net I2C3_SDA: 3983.56,4131.97 3973.6,4095.67 3980.67,4088.6 4016.97,4098.56
  pour cut-out net SPI2_MISO: 3902.65,4158.98 3869.41,4162.66 3865.89,4152.04 3887.79,4114.12
  pour cut-out net SPI2_MOSI: 3899.12,4202.79 3937.04,4180.89 3947.66,4184.41 3943.98,4217.65
  pour cut-out net 3V3: 4967.06,4884.01 4954.59,4880 4954.59,4870 4967.06,4865.99
  pour cut-out net 3V3: 4811.5,4663.47 4810,4677.87 4800,4682.45 4795.12,4670.97
  pour cut-out net SPI1_SCL: 4907.94,4665.99 4920.41,4672.5 4920.41,4677.5 4907.94,4684.01
  pour cut-out net SPI1_MOSI: 4907.94,4630.28 4920.41,4636.79 4920.41,4641.79 4907.94,4648.29
  pour cut-out net SPI1_MOSI: 4924.98,4474.37 4928.79,4485.25 4925.25,4488.79 4914.37,4484.98
  pour cut-out net SPI1_SCL: 4965.94,4474.37 4969.75,4485.25 4966.21,4488.79 4955.33,4484.98
  pour cut-out net UART1_TX: 4879.37,4460.02 4888.49,4454.44 4895.56,4461.51 4889.98,4470.63
  pour cut-out net UART1_TX: 5300.99,4789.11 5305,4776.64 5315,4776.64 5319.01,4789.11
  pour cut-out net UART1_RX: 5350.99,4787.63 5355,4775.16 5365,4775.16 5369.01,4787.63
  pour cut-out net RST: 3915.99,4882.06 3920,4870 3930,4870 3934.01,4882.06
  pour cut-out net I2C3_SCL: 4217.94,4415.99 4230.41,4420 4230.41,4430 4217.94,4434.01
  pour cut-out net SPI2_SCL: 4818.39,4242.5 4808,4240 4808,4230 4818.39,4227.5
  pour cut-out net SPI2_SCL: 4401.61,4227.5 4412,4230 4412,4240 4401.61,4242.5
  pour cut-out net UART3_RX: 4932.5,4027.08 4930,4037.46 4920,4037.46 4917.5,4027.08
  pour cut-out net KEY: 4972.5,4026.61 4970,4037 4960,4037 4957.5,4026.61
  pour cut-out net KEY: 5887.89,4905.67 5881.95,4894.02 5889.07,4886.99 5900.72,4893.02
  pour cut-out net UART3_RX: 4692.94,4480.99 4705.41,4485 4705.41,4495 4692.94,4499.01
  pour cut-out net UART1_RX: 4849.37,4445.02 4858.49,4439.44 4865.56,4446.51 4859.98,4455.63
  pour cut-out net I2C3_SCL: 4622.56,4328.86 4614.87,4334.21 4607.8,4327.14 4613.15,4319.44
  pour cut-out net SPI2_MISO: 4616.49,4286.66 4607.27,4285 4607.27,4275 4616.49,4273.34
  pour cut-out net SPI2_MOSI: 4639.13,4266.66 4629.91,4265 4629.91,4255 4639.13,4253.34
  pour cut-out net I2C3_SDA: 4639.13,4306.66 4629.91,4305 4629.91,4295 4639.13,4293.34
  pour cut-out net RST: 4651.66,4345.87 4650,4355.09 4640,4355.09 4638.34,4345.87
  pour cut-out net I2C3_SCL: 4261.8,4412.62 4254.11,4417.97 4247.03,4410.89 4252.38,4403.2
  pour cut-out net I2C3_SCL: 4263.74,4395.24 4273.81,4395 4278.48,4405 4269.38,4407.3
Bottom Layer:
  region net BAT-: 3995,3700 4030,3700 4030,3765 3995,3765
  region net VCC: 3840,3700 3975,3700 3975,3860 3840,3860
  region net VCC: 3935,3630 3975,3630 3975,3720 3935,3720
  region net BAT-: 4150,3760 4260,3760 4260,3860 4150,3860
  region net BAT-: 3995,3760 3995,4030 4110,4145 4110,4268.68 4116.31,4274.99 4349.53,4274.99 4349.53,4108.09 4218.09,4108.09 4165,4055 4165,3760.36 4164.64,3760
  region net VCC: 5233.2,3881.8 5100.28,3881.8 5035,4000 4547.48,4000 4518.08,4029.4 4518.08,4066.92 4500,4085 4400,4085 4365,4095 4245,4095 4190,4040 4190,3950 4205,3920 4845,3920 4860,3905 4860,3840 4875,3825 5002.94,3825 5010,3832.06 5227.06,3832.06 5245,3840 5245,3870
  region net $1N6781: 5355,3720 5395,3720 5415,3740 5475,3740 5535.5,3800.5 5535.5,3825 5495,3825 5490,3820 5380,3820 5375,3815 5375,3790 5371.36,3768.18 5355,3760
  region net SER.5V: 5725,3755 5820,3755 5845,3780 5935,3780 5940,3785 5940,3848.83 5951.17,3860 5970,3860 5975,3865 5975,3985 5960,4000 5960,4560 5945,4575 5885,4575 5870,4560 5870,3965 5860,3955 5860,3915 5835,3895 5810,3895
  region net $1N6774: 4450,4105 4450,4150 4440,4160 4395,4160 4395,4205 4480,4205 4495,4220 4495,4290 4595,4290 4595,4230 4546.08,4230 4515,4198.92 4515,4163.08 4500,4148.08 4500,4105
  region net 5V: 4495,4375 4495,4438.57 4491.64,4441.93 4491.64,4563.36 4470,4585 4455,4585 4445,4595 4445,4675 4545,4675 4545,4645 4566.96,4637.68 4627.03,4637.68 4627.03,4602.93 4547.93,4602.93 4540,4595 4540,4505 4545,4500 4581.53,4499.36 4581.53,4449.46 4594.9,4436.09 4595,4375
  region net 3V3: 4696.39,4600 4745,4600 4750,4590 4845,4590 4845,4670 4750,4670 4745,4665 4745,4645 4735,4635 4695,4635 4690,4640 4655,4640
  pour cut-out net FB: 4601.1,4047.6 4586.1,4053.05 4586.1,4032.15 4601.1,4037.6
  pour cut-out net $1N6773: 4570,4142.85 4560,4142.85 4547.5,4127.85 4582.5,4127.85
  pour cut-out net FB: 4660.68,4072.01 4650.68,4072.01 4639.8,4057.01 4671.56,4057.01
  pour cut-out net FB: 4624.8,4047.6 4624.8,4037.6 4639.8,4025.1 4639.8,4057.01
  pour cut-out net 5V: 4686.03,4174.66 4672.01,4185.54 4672.01,4153.78 4686.03,4164.66
  pour cut-out net FB: 4660.68,4079.46 4672.01,4094.46 4638.18,4094.46 4650.68,4079.46
  pour cut-out net 5V: 4687.28,4174.66 4687.28,4164.66 4702.28,4152.16 4702.28,4183.31
  pour cut-out net $1N6767: 4310.44,3764.73 4311.14,3764.82 4281.62,3764.82 4303.36,3757.65
  pour cut-out net $1N6767: 4311.9,3753.45 4301.9,3753.45 4289.4,3738.45 4324.4,3738.45
  pour cut-out net 5V: 4418.25,4630 4418.25,4610 4448.25,4597.8 4448.25,4655
  pour cut-out net 5V: 4504.4,4679.4 4479.4,4672.6 4541.75,4672.6 4524.4,4679.4
  pour cut-out net $1N6785: 5195,3778.7 5205,3778.7 5217.5,3793.7 5182.5,3793.7
  pour cut-out net SERVO_EN: 5150.34,3910 5150.34,3900 5172.2,3893.7 5172.2,3916.3
  pour cut-out net $1N6783: 5196,3981.3 5183.5,3966.3 5218.5,3966.3 5206,3981.3
  pour cut-out net $1N6786: 5370.55,3922.38 5390.2,3893.7 5390.2,3916.3 5380.16,3926.91
  pour cut-out net VREF1: 5472.93,3960 5447.8,3966.3 5447.8,3943.7 5472.93,3950
  pour cut-out net $1N6783: 5196,3987.28 5206,3987.28 5213.19,4002.28 5183.5,4002.28
  pour cut-out net $1N6786: 5367.72,4025 5352.72,4035.75 5352.72,4004.25 5367.72,4015
  pour cut-out net $1N6786: 5330,3989.25 5340,3989.25 5352.5,4004.25 5317.5,4004.25
  pour cut-out net $1N6779: 5447.28,4084.66 5447.28,4074.66 5462.28,4062.16 5462.28,4093.31
  pour cut-out net $1N6779: 5442.01,4084.66 5427.01,4095.54 5427.01,4063.78 5442.01,4074.66
  pour cut-out net $1N6786: 5377.99,4025 5377.99,4015 5392.99,4004.46 5392.99,4036.22
  pour cut-out net $1N6785: 5286.69,3735 5301.69,3722.5 5301.69,3757.5 5286.69,3745
  pour cut-out net VREF1: 5789.46,3940 5789.46,3930 5804.46,3917.99 5804.46,3952.01
  pour cut-out net VREF1: 5577.99,3995 5577.99,3985 5592.99,3974.46 5592.99,4006.22
  pour cut-out net VREF1: 5642.01,3995.34 5627.01,4006.22 5627.01,3974.46 5642.01,3985.34
  pour cut-out net SERVO_EN: 5142.61,3919.8 5132.01,3948.08 5106.13,3924.46 5134.41,3913.86
  pour cut-out net SERVO_EN: 5134.41,3966.82 5106.13,3956.22 5132.01,3932.6 5142.61,3960.88
  pour cut-out net 5V: 4591.23,4451.69 4591.23,4465.84 4580.63,4497.72 4562.97,4462.28
  pour cut-out net 5V: 4965.88,4807.61 4937.6,4797.01 4961.22,4771.13 4971.82,4799.41
  pour cut-out net 5V: 4939.34,4744.99 4951.34,4744.99 4961.22,4762.99 4929.46,4762.99
  pour cut-out net $2N28742: 4999.66,4747.99 5009.66,4747.99 5020.54,4762.99 4988.78,4762.99
  pour cut-out net 5V: 4939.34,4684.99 4951.34,4684.99 4961.22,4702.99 4929.46,4702.99
  pour cut-out net 5V: 4939.34,4755.01 4929.46,4737.01 4961.22,4737.01 4951.34,4755.01
  pour cut-out net $2N28742: 4999.66,4752.01 4988.78,4737.01 5020.54,4737.01 5009.66,4752.01
  pour cut-out net $2N28742: 4999.66,4687.99 5009.66,4687.99 5020.54,4702.99 4988.78,4702.99
  pour cut-out net 5V: 4939.34,4695.01 4929.46,4677.01 4961.22,4677.01 4951.34,4695.01
  pour cut-out net $2N28742: 4984.12,4632.39 5012.4,4642.99 4988.78,4668.87 4978.18,4640.59
  pour cut-out net $2N28742: 4999.66,4692.01 4988.78,4677.01 5020.54,4677.01 5009.66,4692.01
  pour cut-out net $2N28742: 5144.72,4689.25 5154.72,4689.25 5167.22,4704.25 5132.22,4704.25
  pour cut-out net I2C3_SDA: 3991.38,4109.16 4010,4085 4020,4085 4038.62,4109.16
  pour cut-out net SPI2_MISO: 3886.06,4142.44 3867.7,4104.77 3872.24,4095.17 3906.27,4099.73
  pour cut-out net SPI2_MOSI: 3892.29,4251.82 3861.07,4232.4 3861.9,4222.4 3896.19,4204.74
  pour cut-out net 5V: 4035.84,4306.38 4068.55,4320 4068.55,4340 4035.84,4353.62
  pour cut-out net SPI2_SCL: 3892.43,4351.97 3861.1,4332.6 3861.86,4322.6 3896.03,4304.86
  pour cut-out net SPI2_SCL: 3891.38,4309.16 3910,4290 3920,4290 3938.62,4309.16
  pour cut-out net SPI2_CS: 3938.62,4450.84 3920,4483.55 3910,4483.55 3891.38,4450.84
  pour cut-out net SPI2_CS: 3910,4514.25 3920,4514.25 3928.35,4529.25 3897.5,4529.25
  pour cut-out net SPI2_SCL: 3860.75,4322.6 3860.75,4332.6 3845.75,4343.35 3845.75,4311.85
  pour cut-out net SPI2_MOSI: 3860.75,4232.4 3845.75,4243.15 3845.75,4211.65 3860.75,4222.4
  pour cut-out net SPI2_MISO: 3860,4083.15 3849.25,4068.15 3880.75,4068.15 3870,4083.15
  pour cut-out net 5V: 3941.38,4724.16 3955,4691.45 3975,4691.45 3988.62,4724.16
  pour cut-out net 5V: 5560,4454.37 5580,4454.37 5583.47,4505.63 5552.37,4505.63
  pour cut-out net 5V: 5560,4535.63 5552.37,4505.63 5583.47,4505.63 5580,4535.63
  pour cut-out net 5V: 5175.63,4850 5175.63,4870 5145.63,4873.47 5145.63,4842.37
  pour cut-out net 5V: 5119.46,4894.69 5103.16,4882.7 5124.37,4873.47 5145.63,4873.47
  pour cut-out net 5V: 3955,4715.63 3947.37,4685.63 3978.47,4685.63 3975,4715.63
  pour cut-out net $1N6767: 4315.84,3712.49 4311.9,3725.03 4301.9,3725.2 4297.83,3712.79
  pour cut-out net SERVO_EN: 5198.39,4157.5 5188,4155 5188,4145 5198.39,4142.5
  pour cut-out net SPI2_SCL: 4402.5,4241.61 4400,4252 4390,4252 4387.5,4241.61

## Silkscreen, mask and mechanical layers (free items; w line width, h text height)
Top Overlay:
  lines w5: 4741.71,4735 4750,4743.29 ; 4758.29,4735 4750,4743.29 ; 4775,4760 4785,4755 ; 4775,4760.87 4785,4770 ; 4780,4760 cw(c4787.24,4721.26) 4825,4710 ; 4800,4676.71 4808.29,4685 ; 4800,4693.29 4808.29,4685 ; 4750,4743.29 4750,4685 4808.29,4685
  text "RST" at 3787.48,4979.36 h51.1 r270
  text "KEY" at 6097.52,4825.64 h51.1 r90
  text "Y" at 4734.79,4754.87 h53.52
  text "X" at 4845.21,4705.13 h53.52 r180
  text "V2.0" at 5765.04,3833.11 h38.33
  text "CB-L4" at 5255,3805 h120
  text "qiaNwan" at 5255,3685 h120
  text "JLCJLCJLCJLC" at 4461.49,3654.61 h28.11
Bottom Overlay:
  lines w5: 4895.47,4165.94 5215,4165.94 5215,4485.47 4895.47,4485.47 4895.47,4165.94
  text "2022.8.15" at 5143.95,3580.73 h45.99
  text "Designed by qianwan" at 5500.77,3514.86 h43.44
Mechanical 1:
  lines w1: 4860,4600 4860,4840 4955,4840 4955,4820 4880,4820 4880,4620 4955,4620 4955,4600 4860,4600 ; 4994.06,4600 4994.06,4620 5069.06,4620 5069.06,4820 4994.06,4820 4994.06,4840 5089.06,4840 5089.06,4600 4994.06,4600
  lines w10: 3765,3465.83 6127.2,3465.83 6127.2,5080 3765,5080 3765,3465.83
